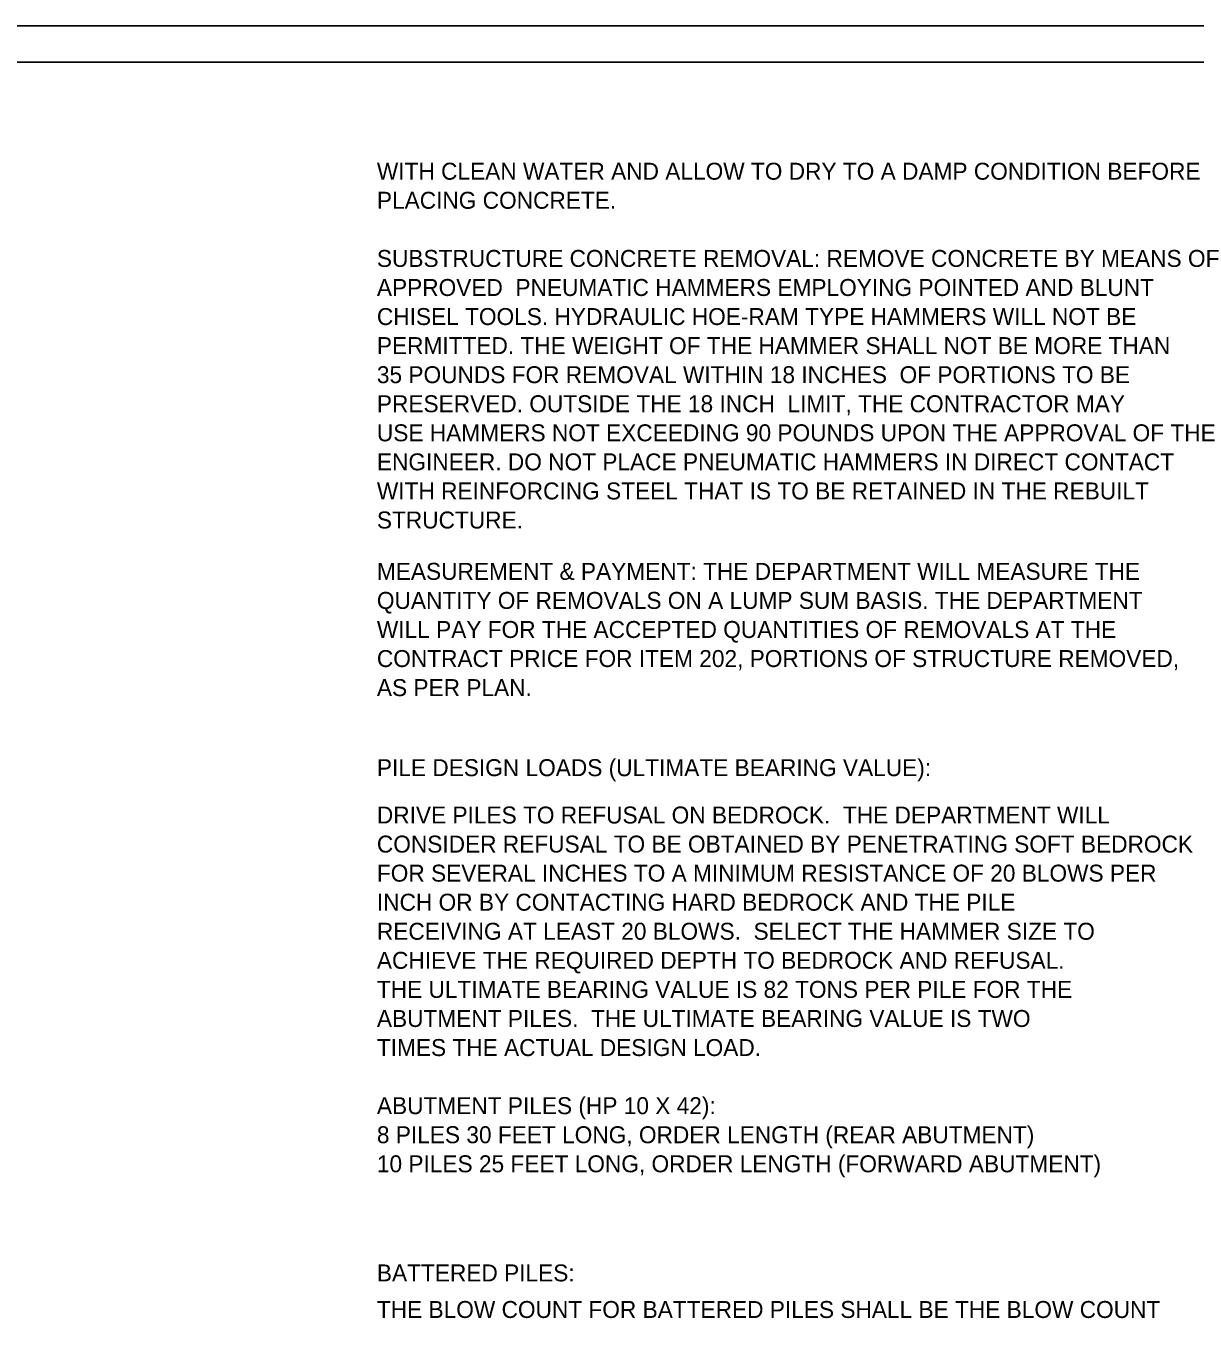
# Model space of a CAD drawing. Extents: x -70.8 to -34.9, y -11.3 to 10.7.
# Drawn here: x -49.38 to -39.72, y -0.19 to 10.53 of the extents above; entities that cross this region are included whole.
import ezdxf

# ---------------------------------------------------------------- set-up
doc = ezdxf.new("R2010")
doc.units = 0
for name, color, linetype in [('BR_P_Gen_Text', 7, 'Continuous'), ('SH_Border', 7, 'Continuous'), ('SH_Cut_Line', 7, 'Continuous')]:
    doc.layers.add(name, color=color, linetype=linetype)

msp = doc.modelspace()

# ---------------------------------------------------------------- linework, layer by layer
at = {"layer": 'SH_Border'}
msp.add_lwpolyline([(-67.571, 10.226), (-36.071, 10.226), (-36.071, -10.774), (-67.571, -10.774)], close=True, dxfattribs=at)
at = {"layer": 'SH_Cut_Line'}
msp.add_lwpolyline([(-35.509, -11.124), (-69.509, -11.124), (-69.509, 10.526), (-35.509, 10.526)], close=True, dxfattribs=at)

# ---------------------------------------------------------------- texts
at = {"layer": 'BR_P_Gen_Text'}
for s, p in [('WITH CLEAN WATER AND ALLOW TO DRY TO A DAMP CONDITION BEFORE ', (-46.479, 9.256)), ('PLACING CONCRETE.', (-46.479, 9.016)), ('SUBSTRUCTURE CONCRETE REMOVAL: REMOVE CONCRETE BY MEANS OF ', (-46.479, 8.536)), ('APPROVED  PNEUMATIC HAMMERS EMPLOYING POINTED AND BLUNT ', (-46.479, 8.296)), ('CHISEL TOOLS. HYDRAULIC HOE-RAM TYPE HAMMERS WILL NOT BE ', (-46.479, 8.056)), ('PERMITTED. THE WEIGHT OF THE HAMMER SHALL NOT BE MORE THAN ', (-46.479, 7.816)), ('35 POUNDS FOR REMOVAL WITHIN 18 INCHES  OF PORTIONS TO BE ', (-46.479, 7.576)), ('PRESERVED. OUTSIDE THE 18 INCH  LIMIT, THE CONTRACTOR MAY ', (-46.479, 7.336)), ('USE HAMMERS NOT EXCEEDING 90 POUNDS UPON THE APPROVAL OF THE ', (-46.479, 7.096)), ('ENGINEER. DO NOT PLACE PNEUMATIC HAMMERS IN DIRECT CONTACT ', (-46.479, 6.856)), ('WITH REINFORCING STEEL THAT IS TO BE RETAINED IN THE REBUILT ', (-46.479, 6.616)), ('STRUCTURE.', (-46.479, 6.376)), ('MEASUREMENT & PAYMENT: THE DEPARTMENT WILL MEASURE THE ', (-46.479, 5.952)), ('QUANTITY OF REMOVALS ON A LUMP SUM BASIS. THE DEPARTMENT ', (-46.479, 5.712)), ('WILL PAY FOR THE ACCEPTED QUANTITIES OF REMOVALS AT THE ', (-46.479, 5.472)), ('CONTRACT PRICE FOR ITEM 202, PORTIONS OF STRUCTURE REMOVED, ', (-46.479, 5.232)), ('AS PER PLAN.', (-46.479, 4.992)), ('PILE DESIGN LOADS (ULTIMATE BEARING VALUE):', (-46.479, 4.331)), ('DRIVE PILES TO REFUSAL ON BEDROCK.  THE DEPARTMENT WILL ', (-46.479, 3.94)), ('CONSIDER REFUSAL TO BE OBTAINED BY PENETRATING SOFT BEDROCK ', (-46.479, 3.7)), ('FOR SEVERAL INCHES TO A MINIMUM RESISTANCE OF 20 BLOWS PER ', (-46.479, 3.46)), ('INCH OR BY CONTACTING HARD BEDROCK AND THE PILE ', (-46.479, 3.22)), ('RECEIVING AT LEAST 20 BLOWS.  SELECT THE HAMMER SIZE TO ', (-46.479, 2.98)), ('ACHIEVE THE REQUIRED DEPTH TO BEDROCK AND REFUSAL.', (-46.479, 2.74)), ('THE ULTIMATE BEARING VALUE IS 82 TONS PER PILE FOR THE ', (-46.479, 2.5)), ('ABUTMENT PILES.  THE ULTIMATE BEARING VALUE IS TWO ', (-46.479, 2.26)), ('TIMES THE ACTUAL DESIGN LOAD.', (-46.479, 2.02)), ('ABUTMENT PILES (HP 10 X 42):', (-46.479, 1.54)), ('8 PILES 30 FEET LONG, ORDER LENGTH (REAR ABUTMENT)', (-46.479, 1.3)), ('10 PILES 25 FEET LONG, ORDER LENGTH (FORWARD ABUTMENT)', (-46.479, 1.06)), ('BATTERED PILES:', (-46.479, 0.159)), ('THE BLOW COUNT FOR BATTERED PILES SHALL BE THE BLOW COUNT', (-46.479, -0.143))]:
    msp.add_text(s, height=0.14, dxfattribs=at).set_placement(p)

doc.saveas('drawing.dxf')
